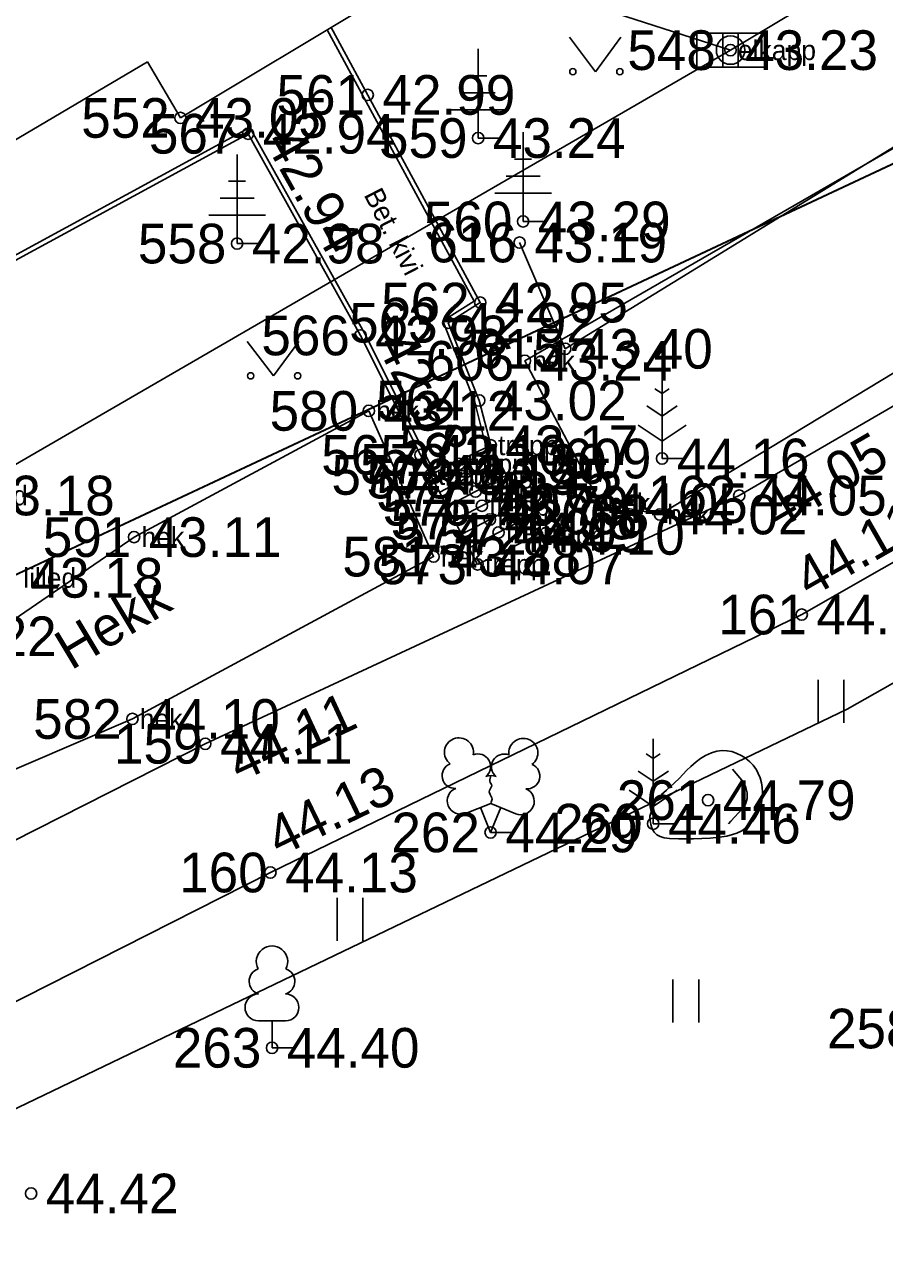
# Model space of a CAD drawing. Extents: x 505800 to 507326, y 6540058 to 6542128.
# Drawn here: x 506360.03 to 506375.21, y 6540333.29 to 6540354.69 of the extents above; entities that cross this region are included whole.
import ezdxf

# ---------------------------------------------------------------- set-up
doc = ezdxf.new("R2010")
doc.units = 0
for name, color, linetype in [('AED', 7, 'Continuous'), ('ELRAJATISMP', 7, 'Continuous'), ('HALJASTUS', 7, 'Continuous'), ('HOONE', 7, 'Continuous'), ('KORGUS-EH2000', 7, 'Continuous'), ('MAAMUDEL', 7, 'Continuous'), ('MOOTKORG-EH2000', 7, 'Continuous'), ('MOOTMPUNKT', 7, 'Continuous'), ('MOOTNR', 7, 'Continuous'), ('MPOHULIIN', 7, 'Continuous'), ('PIIR', 7, 'Continuous'), ('POST', 7, 'Continuous'), ('PUU', 7, 'Continuous'), ('RAJATIS', 7, 'Continuous'), ('RELJEEF', 7, 'Continuous'), ('TEE', 7, 'Continuous')]:
    doc.layers.add(name, color=color, linetype=linetype)

msp = doc.modelspace()

# ---------------------------------------------------------------- linework, layer by layer
at = {"layer": 'AED'}
msp.add_lwpolyline([(506368.771, 6540350.837), (506369.577, 6540348.962), (506376.866, 6540353.439)], dxfattribs=at)
at = {"layer": 'ELRAJATISMP'}
for p, q in [((506372.358, 6540354.532), (506372.358, 6540353.935)), ((506372.629, 6540354.532), (506372.629, 6540353.935))]:
    msp.add_line(p, q, dxfattribs=at)
msp.add_lwpolyline([(506371.896, 6540354.532), (506373.091, 6540354.532), (506373.091, 6540353.935), (506371.896, 6540353.935)], close=True, dxfattribs=at)
at = {"layer": 'HALJASTUS'}
for p, q in [((506369.649, 6540354.46), (506370.112, 6540353.853)), ((506370.112, 6540353.853), (506370.558, 6540354.46)), ((506363.964, 6540349.092), (506364.427, 6540348.485)), ((506364.427, 6540348.485), (506364.873, 6540349.092)), ((506374.04, 6540343.118), (506374.04, 6540342.357)), ((506374.495, 6540343.118), (506374.495, 6540342.357)), ((506365.552, 6540339.272), (506365.552, 6540338.511)), ((506366.007, 6540339.272), (506366.007, 6540338.511)), ((506371.477, 6540337.83), (506371.477, 6540337.069)), ((506371.933, 6540337.83), (506371.933, 6540337.069))]:
    msp.add_line(p, q, dxfattribs=at)
for points in [[(506383.074, 6540362.871), (506387.104, 6540358.456), (506388.363, 6540356.347), (506379.473, 6540351.019), (506371.247, 6540346.037), (506370.193, 6540346.236), (506368.863, 6540348.749), (506383.542, 6540357.221), (506381.795, 6540361.969), (506383.074, 6540362.871)], [(506366.11, 6540347.866), (506361.968, 6540345.638), (506356.585, 6540341.95), (506351.827, 6540339.404), (506349.779, 6540343.223), (506348.059, 6540341.477), (506349.272, 6540338.372), (506350.597, 6540336.346), (506357.184, 6540340.389), (506361.938, 6540342.428), (506367.253, 6540345.293), (506366.11, 6540347.866)]]:
    msp.add_lwpolyline(points, dxfattribs=at)
for centre in [(506369.711, 6540353.853), (506370.54, 6540353.853), (506364.026, 6540348.485), (506364.855, 6540348.485)]:
    msp.add_circle(centre, 0.055, dxfattribs=at)
at = {"layer": 'HOONE'}
for p, q in [((506362.786, 6540353.037), (506366.239, 6540355.108)), ((506362.205, 6540354.024), (506356.142, 6540350.457)), ((506362.786, 6540353.037), (506362.205, 6540354.024))]:
    msp.add_line(p, q, dxfattribs=at)
at = {"layer": 'KORGUS-EH2000'}
for centre in [(506372.493, 6540354.233), (506366.092, 6540353.442), (506362.786, 6540353.037), (506363.98, 6540352.757), (506368.04, 6540352.682), (506368.833, 6540351.21), (506363.785, 6540350.819), (506368.771, 6540350.837), (506368.078, 6540349.777), (506367.513, 6540349.423), (506365.964, 6540349.197), (506369.577, 6540348.962), (506368.863, 6540348.749), (506368.058, 6540348.05), (506366.11, 6540347.866), (506368.261, 6540347.259), (506367.02, 6540347.089), (506371.285, 6540347.025), (506367.705, 6540346.929), (506367.201, 6540346.736), (506367.818, 6540346.672), (506367.992, 6540346.443), (506368.106, 6540346.191), (506370.193, 6540346.236), (506372.647, 6540346.37), (506368.246, 6540345.948), (506371.247, 6540346.037), (506361.968, 6540345.638), (506368.4, 6540345.722), (506369.083, 6540345.677), (506367.253, 6540345.293), (506368.031, 6540345.157), (506373.749, 6540344.271), (506361.938, 6540342.428), (506363.224, 6540341.99), (506372.097, 6540340.995), (506368.259, 6540340.425), (506371.129, 6540340.58), (506364.374, 6540339.718), (506364.402, 6540336.624), (506360.15, 6540334.052)]:
    msp.add_circle(centre, 0.1, dxfattribs=at)
at = {"layer": 'MOOTMPUNKT'}
for centre in [(506372.493, 6540354.233), (506366.092, 6540353.442), (506362.786, 6540353.037), (506363.98, 6540352.757), (506368.04, 6540352.682), (506368.833, 6540351.21), (506363.785, 6540350.819), (506368.771, 6540350.837), (506368.078, 6540349.777), (506367.513, 6540349.423), (506365.964, 6540349.197), (506369.577, 6540348.962), (506368.863, 6540348.749), (506368.058, 6540348.05), (506366.11, 6540347.866), (506368.261, 6540347.259), (506367.02, 6540347.089), (506371.285, 6540347.025), (506367.705, 6540346.929), (506367.201, 6540346.736), (506367.818, 6540346.672), (506367.992, 6540346.443), (506368.106, 6540346.191), (506370.193, 6540346.236), (506372.647, 6540346.37), (506368.246, 6540345.948), (506371.247, 6540346.037), (506361.968, 6540345.638), (506368.4, 6540345.722), (506369.083, 6540345.677), (506367.253, 6540345.293), (506368.031, 6540345.157), (506373.749, 6540344.271), (506361.938, 6540342.428), (506363.224, 6540341.99), (506372.097, 6540340.995), (506368.259, 6540340.425), (506371.129, 6540340.58), (506364.374, 6540339.718), (506364.402, 6540336.624), (506360.15, 6540334.052)]:
    msp.add_circle(centre, 0.1, dxfattribs=at)
at = {"layer": 'MPOHULIIN'}
msp.add_line((506372.493, 6540354.233), (506416.453, 6540380.536), dxfattribs=at)
msp.add_lwpolyline([(506338.064, 6540334.279), (506372.493, 6540354.233), (506366.077, 6540356.302)], dxfattribs=at)
at = {"layer": 'PIIR'}
msp.add_lwpolyline([(506326.14, 6540370.11), (506324.04, 6540375.18), (506354.05, 6540393.57), (506395.54, 6540418.74), (506427.6, 6540438.79), (506429.21, 6540436.36), (506458.7, 6540391.28), (506340.34, 6540335.82)], close=True, dxfattribs=at)
for points in [[(506215.95, 6540254.34), (506268.55, 6540273.9), (506274.54, 6540277.85), (506304.35, 6540308.95), (506340.34, 6540335.82), (506458.7, 6540391.28), (506563.96, 6540420.02)], [(506497.85, 6540391.32), (506462.8, 6540384.69), (506453.27, 6540382.76), (506413.82, 6540364.84), (506374.55, 6540342.6), (506353.59, 6540332.53), (506318.07, 6540309.28), (506308, 6540301.95), (506281.65, 6540275.05), (506272.39, 6540267.75), (506224.13, 6540249.92)], [(506224.13, 6540249.92), (506272.39, 6540267.75), (506281.65, 6540275.05), (506308, 6540301.95), (506318.07, 6540309.28), (506353.59, 6540332.53), (506374.55, 6540342.6), (506413.82, 6540364.84), (506453.27, 6540382.76), (506462.8, 6540384.69), (506495.14, 6540337.45), (506342.85, 6540237.27), (506260.72, 6540195.9), (506215.68, 6540179.69)]]:
    msp.add_lwpolyline(points, dxfattribs=at)
at = {"layer": 'POST'}
msp.add_circle((506372.493, 6540354.233), 0.25, dxfattribs=at)
at = {"layer": 'PUU'}
for p, q in [((506368.04, 6540352.682), (506368.04, 6540354.257)), ((506368.19, 6540353.782), (506367.89, 6540353.782)), ((506368.34, 6540353.482), (506367.74, 6540353.482)), ((506368.54, 6540353.182), (506367.54, 6540353.182)), ((506368.4, 6540352.682), (506368.04, 6540352.682)), ((506368.833, 6540351.21), (506368.833, 6540352.785)), ((506363.785, 6540350.819), (506363.785, 6540352.394)), ((506368.983, 6540352.31), (506368.683, 6540352.31)), ((506363.935, 6540351.919), (506363.635, 6540351.919)), ((506369.133, 6540352.01), (506368.533, 6540352.01)), ((506364.085, 6540351.619), (506363.485, 6540351.619)), ((506369.333, 6540351.71), (506368.333, 6540351.71)), ((506364.285, 6540351.319), (506363.285, 6540351.319)), ((506369.193, 6540351.21), (506368.833, 6540351.21)), ((506364.145, 6540350.819), (506363.785, 6540350.819)), ((506371.285, 6540348.525), (506371.285, 6540347.025)), ((506371.285, 6540348.175), (506371.16, 6540348.258)), ((506371.409, 6540348.258), (506371.285, 6540348.175)), ((506371.285, 6540347.775), (506371.018, 6540347.953)), ((506371.551, 6540347.953), (506371.285, 6540347.775)), ((506370.861, 6540347.615), (506371.285, 6540347.332)), ((506371.285, 6540347.332), (506371.709, 6540347.615)), ((506371.645, 6540347.025), (506371.285, 6540347.025)), ((506371.129, 6540342.08), (506371.129, 6540340.58)), ((506371.129, 6540341.73), (506371.005, 6540341.813)), ((506371.254, 6540341.813), (506371.129, 6540341.73)), ((506371.129, 6540341.33), (506370.863, 6540341.508)), ((506371.396, 6540341.508), (506371.129, 6540341.33)), ((506370.705, 6540341.169), (506371.129, 6540340.886)), ((506371.129, 6540340.886), (506371.554, 6540341.169)), ((506367.819, 6540340.76), (506368.264, 6540340.935)), ((506368.264, 6540340.935), (506368.704, 6540340.755)), ((506368.259, 6540340.425), (506368.084, 6540340.865)), ((506368.259, 6540340.425), (506368.439, 6540340.865)), ((506371.489, 6540340.58), (506371.129, 6540340.58)), ((506368.639, 6540340.425), (506368.259, 6540340.425)), ((506364.642, 6540337.099), (506364.162, 6540337.099)), ((506364.402, 6540336.624), (506364.402, 6540337.099)), ((506364.782, 6540336.624), (506364.402, 6540336.624))]:
    msp.add_line(p, q, dxfattribs=at)
msp.add_lwpolyline([(506368.264, 6540341.43), (506368.244, 6540341.355), (506368.244, 6540341.335), (506368.254, 6540341.305), (506368.274, 6540341.27), (506368.279, 6540341.25), (506368.264, 6540341.215), (506368.239, 6540341.165), (506368.234, 6540341.14), (506368.239, 6540341.125), (506368.249, 6540341.095), (506368.284, 6540341.035), (506368.289, 6540341.015), (506368.284, 6540340.995), (506368.269, 6540340.96), (506368.264, 6540340.935)], dxfattribs=at)
for centre, radius, start, end in [((506367.701, 6540341.839), 0.256, 111.5027, 232.5173), ((506367.701, 6540341.839), 0.256, 350.4856, 111.5002), ((506368.837, 6540341.83), 0.256, 67.6168, 188.6314), ((506368.837, 6540341.83), 0.256, 306.5997, 67.6143), ((506368.036, 6540341.588), 0.224, 308.5041, 111.5725), ((506368.499, 6540341.584), 0.225, 67.7016, 230.5126), ((506367.628, 6540341.427), 0.224, 111.4304, 274.4987), ((506368.905, 6540341.418), 0.224, 264.6183, 67.6866), ((506368.263, 6540341.192), 0.237, 66.7655, 111.5015), ((506367.732, 6540340.983), 0.237, 111.5014, 291.5004), ((506368.793, 6540340.975), 0.237, 247.6166, 67.6155), ((506364.402, 6540338.144), 0.277, 332.5799, 207.4201), ((506364.232, 6540337.796), 0.233, 109.0217, 253.1415), ((506364.572, 6540337.796), 0.233, 286.8508, 70.9859), ((506364.164, 6540337.336), 0.238, 90.0016, 269.3953), ((506364.639, 6540337.336), 0.238, 270.6047, 89.9984)]:
    msp.add_arc(centre, radius, start, end, dxfattribs=at)
at = {"layer": 'RAJATIS'}
for p, q in [((506367.818, 6540346.672), (506368.407, 6540346.977)), ((506367.992, 6540346.443), (506368.537, 6540346.726)), ((506367.818, 6540346.672), (506367.361, 6540346.431)), ((506368.106, 6540346.191), (506368.665, 6540346.481)), ((506367.992, 6540346.443), (506367.493, 6540346.18)), ((506368.106, 6540346.191), (506367.622, 6540345.936)), ((506368.246, 6540345.948), (506368.794, 6540346.233)), ((506368.246, 6540345.948), (506367.752, 6540345.688)), ((506368.4, 6540345.722), (506368.919, 6540345.991)), ((506368.4, 6540345.722), (506367.879, 6540345.447))]:
    msp.add_line(p, q, dxfattribs=at)
msp.add_lwpolyline([(506368.031, 6540345.157), (506369.083, 6540345.677), (506368.261, 6540347.259), (506367.201, 6540346.736)], close=True, dxfattribs=at)
at = {"layer": 'RELJEEF'}
for points in [[(506371.072, 6540340.71), (506371.09, 6540340.785), (506371.112, 6540340.85), (506371.134, 6540340.904), (506371.165, 6540340.961), (506371.216, 6540341.031), (506371.278, 6540341.094), (506371.364, 6540341.171), (506371.501, 6540341.297), (506371.591, 6540341.386), (506371.719, 6540341.518), (506371.791, 6540341.589), (506371.888, 6540341.673), (506371.963, 6540341.728), (506372.052, 6540341.782), (506372.16, 6540341.832), (506372.25, 6540341.859), (506372.346, 6540341.871), (506372.429, 6540341.867), (506372.516, 6540341.851), (506372.592, 6540341.827), (506372.693, 6540341.779), (506372.754, 6540341.74), (506372.836, 6540341.672), (506372.893, 6540341.612), (506372.95, 6540341.53), (506372.983, 6540341.467), (506373.016, 6540341.387), (506373.038, 6540341.303), (506373.051, 6540341.221), (506373.056, 6540341.137), (506373.052, 6540341.045), (506373.038, 6540340.95), (506373.014, 6540340.86), (506372.975, 6540340.766), (506372.932, 6540340.692), (506372.879, 6540340.619), (506372.819, 6540340.554), (506372.764, 6540340.506), (506372.69, 6540340.456), (506372.605, 6540340.413), (506372.53, 6540340.386), (506372.428, 6540340.36), (506372.293, 6540340.34), (506372.135, 6540340.325), (506371.838, 6540340.312), (506371.575, 6540340.311), (506371.419, 6540340.317), (506371.324, 6540340.33), (506371.251, 6540340.353), (506371.192, 6540340.385), (506371.144, 6540340.43), (506371.111, 6540340.486), (506371.088, 6540340.563), (506371.077, 6540340.638), (506371.072, 6540340.71)], [(506372.457, 6540340.58), (506372.499, 6540340.626), (506372.568, 6540340.699), (506372.636, 6540340.772), (506372.703, 6540340.846), (506372.759, 6540340.927), (506372.785, 6540341.024), (506372.785, 6540341.124), (506372.764, 6540341.221), (506372.722, 6540341.312), (506372.659, 6540341.389), (506372.593, 6540341.464), (506372.527, 6540341.54)]]:
    msp.add_lwpolyline(points, dxfattribs=at)
at = {"layer": 'TEE'}
for points in [[(506478.706, 6540392.058), (506464.091, 6540389.4), (506454.678, 6540387.173), (506446.264, 6540384.451), (506435.18, 6540379.372), (506420.092, 6540372.182), (506407.957, 6540366.228), (506394.897, 6540359.329), (506383.759, 6540352.819), (506372.647, 6540346.37), (506363.224, 6540341.99), (506352.182, 6540336.393), (506347.174, 6540333.201), (506340.898, 6540329.111), (506329.323, 6540321.237)], [(506479.167, 6540389.797), (506464.651, 6540387.028), (506455.166, 6540384.708), (506447.071, 6540382.035), (506436.402, 6540377.232), (506421.232, 6540370.083), (506409.03, 6540364.194), (506396.144, 6540357.137), (506385.127, 6540350.766), (506373.749, 6540344.271), (506364.374, 6540339.718), (506353.506, 6540334.212), (506348.479, 6540331.101), (506342.338, 6540327.065), (506330.786, 6540319.25)], [(506368.261, 6540347.259), (506368.058, 6540348.05), (506367.513, 6540349.423), (506368.078, 6540349.777), (506365.447, 6540354.633)], [(506368.182, 6540347.22), (506367.983, 6540348.02), (506367.414, 6540349.455), (506367.972, 6540349.805), (506365.378, 6540354.592)], [(506356.142, 6540350.457), (506356.594, 6540349.573), (506356.964, 6540348.942), (506363.98, 6540352.757), (506365.964, 6540349.197), (506367.02, 6540347.089), (506367.201, 6540346.736)], [(506356.229, 6540350.506), (506356.663, 6540349.613), (506356.993, 6540349.049), (506364.011, 6540352.865), (506366.034, 6540349.235), (506367.092, 6540347.125), (506367.268, 6540346.769)]]:
    msp.add_lwpolyline(points, dxfattribs=at)

# ---------------------------------------------------------------- texts
at = {"layer": 'HALJASTUS'}
msp.add_text('Hekk', height=0.7, rotation=30.9694, dxfattribs=at).set_placement((506360.856, 6540343.278))
at = {"layer": 'KORGUS-EH2000'}
for s, rotation, p in [(' 42.94', 299.1352, (506364.133, 6540352.842)), (' 42.98', 296.6237, (506366.12, 6540349.276)), (' 44.05', 30.1302, (506373.086, 6540345.613)), (' 44.11', 29.7195, (506373.662, 6540344.423)), (' 44.11', 24.9268, (506363.593, 6540341.197)), (' 44.13', 25.9022, (506364.297, 6540339.875))]:
    msp.add_text(s, height=0.7, rotation=rotation, dxfattribs=at).set_placement(p)
for s, p in [(' 43.19', (506368.771, 6540350.487)), (' 43.18', (506359.023, 6540346.022)), (' 43.11', (506361.968, 6540345.288)), (' 44.42', (506360.15, 6540333.702))]:
    msp.add_text(s, height=0.7, dxfattribs=at).set_placement(p)
at = {"layer": 'MAAMUDEL'}
for s, p in [(' elkapp', (506372.493, 6540354.058)), (' hek', (506368.863, 6540348.574)), (' hek', (506366.11, 6540347.691)), (' trepp', (506368.261, 6540347.084)), (' trepp', (506367.705, 6540346.754)), (' trepp', (506367.201, 6540346.561)), (' trepp', (506367.818, 6540346.497)), (' lilled', (506359.023, 6540346.197)), (' trepp', (506367.992, 6540346.268)), (' trepp', (506368.106, 6540346.016)), (' hek', (506370.193, 6540346.061)), (' trepp', (506368.246, 6540345.773)), (' hek', (506371.247, 6540345.862)), (' trepp', (506368.4, 6540345.547)), (' hek', (506361.968, 6540345.463)), (' trepp', (506369.083, 6540345.502)), (' hek', (506367.253, 6540345.118)), (' trepp', (506368.031, 6540344.982)), (' lilled', (506359.881, 6540344.744)), (' hek', (506361.938, 6540342.253))]:
    msp.add_text(s, height=0.35, dxfattribs=at).set_placement(p)
at = {"layer": 'MOOTKORG-EH2000'}
for s, p in [(' 43.23', (506372.493, 6540353.883)), (' 42.99', (506366.092, 6540353.093)), (' 43.05', (506362.786, 6540352.687)), (' 42.94', (506363.98, 6540352.407)), (' 43.24', (506368.04, 6540352.332)), (' 43.29', (506368.833, 6540350.86)), (' 43.19', (506368.771, 6540350.487)), (' 42.98', (506363.785, 6540350.469)), (' 42.95', (506368.078, 6540349.427)), (' 42.92', (506367.513, 6540349.073)), (' 42.98', (506365.964, 6540348.847)), (' 43.40', (506369.577, 6540348.612)), (' 43.24', (506368.863, 6540348.399)), (' 43.02', (506368.058, 6540347.7)), (' 43.12', (506366.11, 6540347.516)), (' 43.17', (506368.261, 6540346.909)), (' 43.10', (506367.02, 6540346.739)), (' 44.16', (506371.285, 6540346.675)), (' 43.30', (506367.705, 6540346.579)), (' 43.15', (506367.201, 6540346.386)), (' 43.45', (506367.818, 6540346.321)), (' 43.18', (506359.023, 6540346.022)), (' 43.62', (506367.992, 6540346.093)), (' 44.05', (506372.647, 6540346.02)), (' 43.79', (506368.106, 6540345.841)), (' 44.05', (506370.193, 6540345.886)), (' 43.95', (506368.246, 6540345.598)), (' 44.02', (506371.247, 6540345.687)), (' 44.09', (506368.4, 6540345.372)), (' 43.11', (506361.968, 6540345.288)), (' 44.10', (506369.083, 6540345.327)), (' 43.88', (506367.253, 6540344.943)), (' 44.07', (506368.031, 6540344.807)), (' 43.18', (506359.881, 6540344.569)), (' 44.11', (506373.749, 6540343.921)), (' 43.22', (506357.999, 6540343.537)), (' 44.10', (506361.938, 6540342.078)), (' 44.11', (506363.224, 6540341.64)), (' 44.79', (506372.097, 6540340.645)), (' 44.46', (506371.129, 6540340.23)), (' 44.29', (506368.259, 6540340.075)), (' 44.13', (506364.374, 6540339.368)), (' 44.40', (506364.402, 6540336.274)), (' 44.42', (506360.15, 6540333.702))]:
    msp.add_text(s, height=0.7, dxfattribs=at).set_placement(p)
at = {"layer": 'MOOTNR'}
for s, p in [('548 ', (506370.673, 6540353.883)), ('561 ', (506364.482, 6540353.093)), ('552 ', (506361.036, 6540352.687)), ('567 ', (506362.23, 6540352.407)), ('559 ', (506366.29, 6540352.332)), ('560 ', (506367.083, 6540350.86)), ('616 ', (506367.161, 6540350.487)), ('558 ', (506362.035, 6540350.469)), ('562 ', (506366.328, 6540349.427)), ('563 ', (506365.763, 6540349.073)), ('566 ', (506364.214, 6540348.847)), ('615 ', (506367.967, 6540348.612)), ('606 ', (506367.114, 6540348.399)), ('564 ', (506366.238, 6540347.7)), ('580 ', (506364.36, 6540347.516)), ('571 ', (506366.651, 6540346.909)), ('565 ', (506365.271, 6540346.739)), ('609 ', (506369.535, 6540346.675)), ('579 ', (506365.955, 6540346.579)), ('570 ', (506365.451, 6540346.386)), ('578 ', (506366.068, 6540346.321)), ('577 ', (506366.243, 6540346.093)), ('162 ', (506371.037, 6540346.02)), ('576 ', (506366.356, 6540345.841)), ('607 ', (506368.443, 6540345.886)), ('575 ', (506366.496, 6540345.598)), ('608 ', (506369.497, 6540345.687)), ('574 ', (506366.581, 6540345.372)), ('591 ', (506360.358, 6540345.288)), ('572 ', (506367.333, 6540345.327)), ('581 ', (506365.643, 6540344.943)), ('573 ', (506366.282, 6540344.807)), ('161 ', (506372.279, 6540343.921)), ('582 ', (506360.188, 6540342.078)), ('159 ', (506361.614, 6540341.64)), ('261 ', (506370.487, 6540340.645)), ('260 ', (506369.38, 6540340.23)), ('262 ', (506366.509, 6540340.075)), ('160 ', (506362.764, 6540339.368)), ('258 ', (506374.196, 6540336.614)), ('263 ', (506362.652, 6540336.274))]:
    msp.add_text(s, height=0.7, dxfattribs=at).set_placement(p)
at = {"layer": 'TEE'}
msp.add_text('Bet. kivi', height=0.35, rotation=297.1924, dxfattribs=at).set_placement((506366.015, 6540351.681))

doc.saveas('drawing.dxf')
